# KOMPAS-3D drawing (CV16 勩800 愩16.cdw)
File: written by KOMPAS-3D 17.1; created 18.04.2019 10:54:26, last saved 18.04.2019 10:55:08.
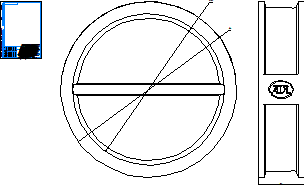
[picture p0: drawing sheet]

Sheet 1: A4, portrait

Title block, sheet 1: name: CV16 Ду800 Ру16; material: Внимание! Данный продукт является объектом авторского права ООО «Торговый Дом АДЛ». / Запрещается изменение, копирование, распространение / (в том числе путем копирования на другие сайты и ресурсы в Интернете) / или любое иное использование информации и объектов без предварительного / согласия правообладателя (ООО «Торговый Дом АДЛ»).; mass: 818,45; sheets: 1; organisation: ООО "Торговый дом АДЛ"; sheet format: A4

Views: Вид 1, Спереди, Проекционный вид 2
Referenced files in \\adlc.lan\data\АДЛ_ПКД\3D-модели\ADL production\Клапаны обратные ГРАНЛОК\CV16\KOMPAS 3D\: CV16 Ду800 Ру16.m3d
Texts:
  user
Dimensions and other numbers on the sheet: 786,8; 911; 241; 1:1; 1; 818,45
